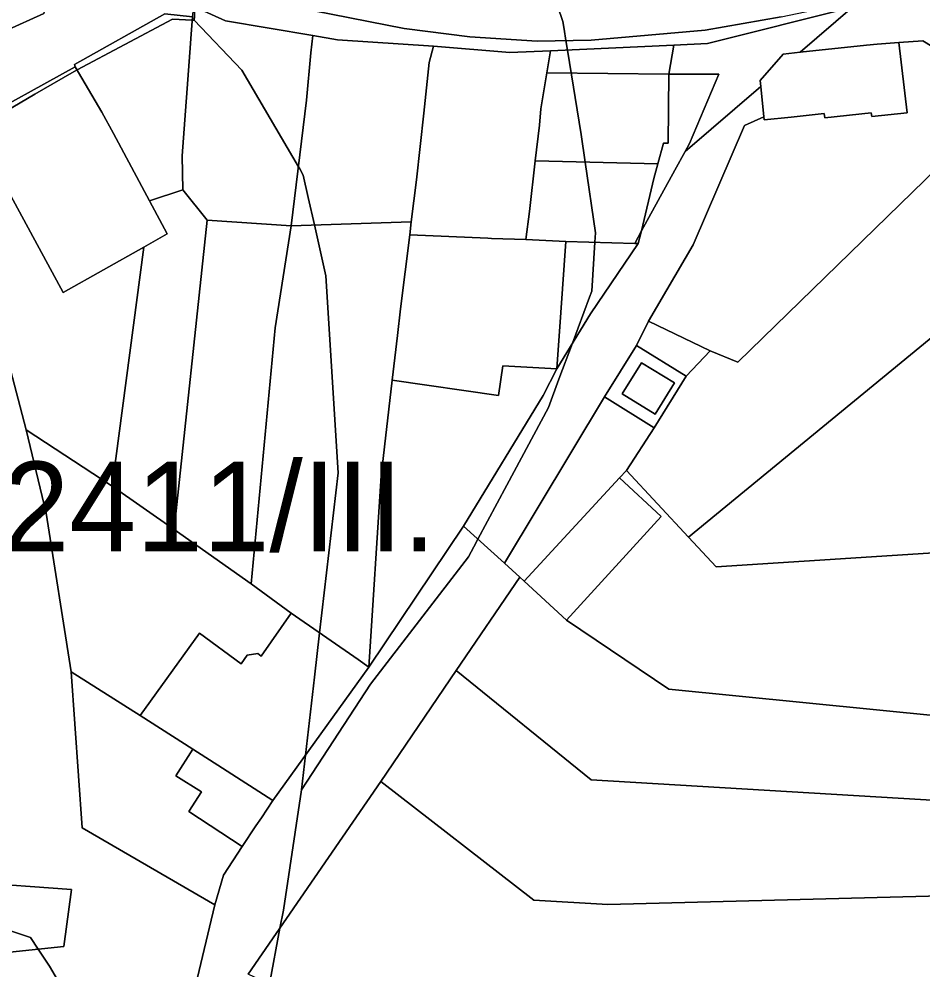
# Model space of a CAD drawing. Extents: x -522079 to -518792, y -1142400 to -1139961.
# Drawn here: x -520623.1 to -520471.9, y -1140957.2 to -1140798.1 of the extents above; entities that cross this region are included whole.
import ezdxf

# ---------------------------------------------------------------- set-up
doc = ezdxf.new("R2010")
doc.units = 0
for name, color, linetype in [('Hranice parcel', 7, 'Continuous'), ('Poz předměty', 7, 'Continuous'), ('Značky bodu BP', 7, 'Continuous'), ('Značky kultur', 7, 'Continuous')]:
    doc.layers.add(name, color=color, linetype=linetype)

msp = doc.modelspace()

# ---------------------------------------------------------------- linework, layer by layer
at = {"layer": 'Hranice parcel'}
for points in [[(-520616.33, -1140786.69), (-520618.93, -1140797.21), (-520638.22, -1140805.93), (-520641.11, -1140798.37), (-520652.69, -1140766.32), (-520657.82, -1140755.57), (-520666.3, -1140735.71), (-520669.12, -1140730.36), (-520634.59, -1140772.65)], [(-520573.94, -1140800.9), (-520588.57, -1140798.45), (-520593.85, -1140796.07), (-520595.39, -1140795.43), (-520594.41, -1140790.88), (-520587.36, -1140792.97), (-520573.73, -1140796.75), (-520558.67, -1140799.71), (-520547.7, -1140801.1), (-520536.39, -1140801.86), (-520527.36, -1140801.68), (-520508.3, -1140799.99), (-520495.6, -1140797.79), (-520487.57, -1140796.09), (-520477.93, -1140793.38), (-520477.5, -1140794.69), (-520478.64, -1140794.97), (-520483.65, -1140796.14), (-520507.9, -1140802.26), (-520513.53, -1140802.52), (-520534.2, -1140803.46), (-520540.96, -1140803.77), (-520553.77, -1140802.66), (-520569.82, -1140801.63)], [(-520479.52, -1140802.35), (-520481.31, -1140802.54), (-520492.42, -1140803.71), (-520483.65, -1140796.14), (-520478.64, -1140794.97), (-520477.5, -1140794.69), (-520471.14, -1140793.15), (-520469.2, -1140792.72), (-520462.48, -1140800.42), (-520444.45, -1140805.57), (-520456.93, -1140810.9), (-520471.87, -1140801.78), (-520475.9, -1140802.08)], [(-520574.26, -1140803.79), (-520575.01, -1140811.7), (-520577.54, -1140832.73), (-520591.61, -1140831.81), (-520595.7, -1140826.74), (-520595.78, -1140821.04), (-520594.39, -1140802.24), (-520594.33, -1140801.38), (-520594.09, -1140797.76), (-520593.85, -1140796.07), (-520588.57, -1140798.45), (-520573.94, -1140800.9)], [(-520510.91, -1140818.98), (-520506.04, -1140807.36), (-520514.4, -1140807.37), (-520513.53, -1140802.52), (-520507.9, -1140802.26), (-520483.65, -1140796.14), (-520492.42, -1140803.71), (-520495.25, -1140804.01), (-520499.12, -1140808.43), (-520499.02, -1140809.41), (-520511.64, -1140820.3)], [(-520613.67, -1140806.13), (-520613.82, -1140805.77), (-520598.71, -1140797.27), (-520594.09, -1140797.76), (-520594.33, -1140801.38), (-520594.39, -1140802.24), (-520595.78, -1140821.04), (-520595.7, -1140826.74), (-520601.28, -1140828.55), (-520607.3, -1140817.32), (-520609.23, -1140813.72)], [(-520573.94, -1140800.9), (-520569.82, -1140801.63), (-520553.77, -1140802.66), (-520554.47, -1140805.42), (-520555.39, -1140813.9), (-520556.61, -1140825.03), (-520557.47, -1140832.08), (-520577.54, -1140832.73), (-520575.01, -1140811.7), (-520574.26, -1140803.79)], [(-520507.49, -1140853.67), (-520517.77, -1140848.71), (-520510.31, -1140835.9), (-520501.75, -1140815.97), (-520498.5, -1140814.52), (-520498.45, -1140815.01), (-520493.9, -1140814.54), (-520488.38, -1140813.94), (-520488.31, -1140814.67), (-520480.51, -1140813.85), (-520480.44, -1140814.43), (-520474.54, -1140813.83), (-520475.9, -1140802.08), (-520471.87, -1140801.78), (-520456.93, -1140810.9), (-520502.85, -1140855.53)], [(-520540.96, -1140803.77), (-520534.2, -1140803.46), (-520534.78, -1140807.16), (-520535.78, -1140813.17), (-520536.03, -1140815.9), (-520536.72, -1140821.88), (-520537.7, -1140830.34), (-520538.32, -1140835.02), (-520544.03, -1140834.85), (-520544.69, -1140834.83), (-520557.73, -1140834.26), (-520557.47, -1140832.08), (-520556.61, -1140825.03), (-520555.39, -1140813.9), (-520554.47, -1140805.42), (-520553.77, -1140802.66)], [(-520534.78, -1140807.16), (-520534.2, -1140803.46), (-520513.53, -1140802.52), (-520514.4, -1140807.37)], [(-520488.38, -1140813.94), (-520493.9, -1140814.54), (-520498.45, -1140815.01), (-520498.5, -1140814.52), (-520499.02, -1140809.41), (-520499.12, -1140808.43), (-520495.25, -1140804.01), (-520492.42, -1140803.71), (-520481.31, -1140802.54), (-520479.52, -1140802.35), (-520475.9, -1140802.08), (-520474.54, -1140813.83), (-520480.44, -1140814.43), (-520480.51, -1140813.85), (-520488.31, -1140814.67)], [(-520615.7, -1140843.89), (-520626.71, -1140823.74), (-520631.12, -1140815.76), (-520613.67, -1140806.13), (-520609.23, -1140813.72), (-520607.3, -1140817.32), (-520601.28, -1140828.55), (-520598.3, -1140834.1), (-520602.23, -1140836.31)], [(-520536.72, -1140821.88), (-520536.03, -1140815.9), (-520535.78, -1140813.17), (-520534.78, -1140807.16), (-520514.4, -1140807.37), (-520514.48, -1140818.9), (-520515.29, -1140818.89), (-520516.23, -1140822.4)], [(-520514.4, -1140807.37), (-520506.04, -1140807.36), (-520510.91, -1140818.98), (-520511.64, -1140820.3), (-520513.38, -1140823.43), (-520518.98, -1140833.57), (-520516.87, -1140824.81), (-520516.23, -1140822.4), (-520515.29, -1140818.89), (-520514.48, -1140818.9)], [(-520511.64, -1140820.3), (-520499.02, -1140809.41), (-520498.5, -1140814.52), (-520501.75, -1140815.97), (-520510.31, -1140835.9), (-520517.77, -1140848.71), (-520519.8, -1140852.78), (-520525.13, -1140861.38), (-520541.88, -1140889.2), (-520548.74, -1140883.02), (-520535.38, -1140861.16), (-520533.13, -1140856.68), (-520527.5, -1140847.46), (-520519.49, -1140835.7), (-520518.98, -1140833.57), (-520513.38, -1140823.43)], [(-520542.88, -1140861.11), (-520560.66, -1140858.55), (-520559.8, -1140851.08), (-520559.29, -1140846.65), (-520557.73, -1140834.26), (-520544.69, -1140834.83), (-520544.03, -1140834.85), (-520538.32, -1140835.02), (-520531.62, -1140835.37), (-520532.45, -1140847.23), (-520533.13, -1140856.68), (-520542.18, -1140856.15)], [(-520517.77, -1140848.71), (-520507.49, -1140853.67), (-520511.48, -1140857.9), (-520519.8, -1140852.78)], [(-520519.8, -1140852.78), (-520511.48, -1140857.9), (-520516.84, -1140866.53), (-520525.13, -1140861.38)], [(-520518.94, -1140855.65), (-520513.44, -1140859.04), (-520516.67, -1140864.28), (-520522.17, -1140860.86)], [(-520513.44, -1140859.04), (-520518.94, -1140855.65), (-520522.17, -1140860.86), (-520516.67, -1140864.28)], [(-520516.84, -1140866.53), (-520521.46, -1140873.68), (-520522.62, -1140874.92), (-520538.57, -1140892.18), (-520539.31, -1140891.51), (-520541.88, -1140889.2), (-520525.13, -1140861.38)], [(-520538.57, -1140892.18), (-520522.62, -1140874.92), (-520515.64, -1140881.37), (-520531.52, -1140898.7)], [(-520602.83, -1140914.7), (-520592.91, -1140900.92), (-520585.91, -1140906.02), (-520584.9, -1140904.6), (-520583.16, -1140904.29), (-520582.61, -1140904.74), (-520577.55, -1140897.54), (-520566.38, -1140905.28), (-520564.56, -1140906.56), (-520580.62, -1140928.87), (-520589.05, -1140923.49), (-520594.01, -1140920.33)], [(-520596.85, -1140924.77), (-520594.01, -1140920.33), (-520589.05, -1140923.49), (-520580.62, -1140928.87), (-520582.55, -1140931.77), (-520583.47, -1140933.16), (-520585.74, -1140936.61), (-520594.7, -1140930.72), (-520592.56, -1140927.47)]]:
    msp.add_lwpolyline(points, close=True, dxfattribs=at)
for points in [[(-520638.22, -1140805.93), (-520618.93, -1140797.21), (-520616.33, -1140786.69), (-520595.39, -1140795.43), (-520593.85, -1140796.07), (-520594.09, -1140797.76), (-520598.71, -1140797.27), (-520613.82, -1140805.77), (-520613.67, -1140806.13), (-520631.12, -1140815.76)], [(-520495.6, -1140797.79), (-520508.3, -1140799.99), (-520527.36, -1140801.68), (-520536.39, -1140801.86), (-520547.7, -1140801.1), (-520558.67, -1140799.71), (-520573.73, -1140796.75)], [(-520594.75, -1140964.79), (-520590.36, -1140946.34), (-520588.9, -1140941.38), (-520585.74, -1140936.61), (-520583.47, -1140933.16), (-520582.55, -1140931.77), (-520580.62, -1140928.87), (-520564.56, -1140906.56), (-520548.74, -1140883.02), (-520541.88, -1140889.2), (-520539.31, -1140891.51), (-520549.95, -1140907.16), (-520562.58, -1140925.73), (-520584.75, -1140957.97)]]:
    msp.add_lwpolyline(points, dxfattribs=at)
at = {"layer": 'Poz předměty'}
for points in [[(-520679.92, -1141124.76), (-520699.09, -1140943.92), (-520632.04, -1140920.85), (-520634.37, -1140902.81), (-520641.23, -1140863.72), (-520646.19, -1140843.58), (-520650.7, -1140826.31), (-520634.79, -1140817.77), (-520621.9, -1140866.86), (-520618.56, -1140880.81), (-520614.37, -1140907.34), (-520612.5, -1140933.48), (-520590.36, -1140946.34), (-520594.75, -1140964.79), (-520649.51, -1140960.76), (-520648.03, -1140963.9), (-520620.51, -1141022.34), (-520612.04, -1141047.58), (-520596.21, -1141046.3), (-520599.33, -1141085.41), (-520603.47, -1141094.45), (-520605.48, -1141096), (-520676.95, -1141126.77)], [(-520614.33, -1140943.77), (-520648.15, -1140941.33), (-520646.42, -1140956.53), (-520615.62, -1140953.33)], [(-520615.62, -1140953.33), (-520646.42, -1140956.53), (-520648.15, -1140941.33), (-520614.33, -1140943.77)]]:
    msp.add_lwpolyline(points, close=True, dxfattribs=at)
at = {"layer": 'Značky bodu BP'}
for points in [[(-520626.64, -1140767.02), (-520622.14, -1140770.72), (-520612.6, -1140776.73), (-520595.12, -1140785.42), (-520594.75, -1140790.77), (-520594.66, -1140792.05), (-520594.4, -1140795.84), (-520594.34, -1140796.75), (-520593.97, -1140796.89), (-520593.9, -1140796.91), (-520593.71, -1140796.98), (-520593.74, -1140797.73), (-520593.77, -1140798.35), (-520594.13, -1140798.33), (-520597.42, -1140798.15), (-520613.36, -1140806.66), (-520614.24, -1140807.13), (-520620.42, -1140810.73), (-520630.61, -1140816.68)], [(-520533.02, -1140795.94), (-520532.11, -1140798.57), (-520531.9, -1140799.83), (-520531.59, -1140801.76), (-520531.34, -1140803.33), (-520529.07, -1140817.46), (-520528.39, -1140822.09), (-520526.64, -1140833.91), (-520526.74, -1140835.5), (-520527.25, -1140843.66), (-520527.64, -1140844.7), (-520530.51, -1140852.4), (-520532.76, -1140858.41), (-520534.54, -1140863.15), (-520541.46, -1140876.11), (-520546.32, -1140885.19), (-520547, -1140886.46), (-520547.9, -1140888.13), (-520564.3, -1140909.45), (-520575.83, -1140927.12), (-520575.16, -1140921.29), (-520573.66, -1140908.26), (-520572.8, -1140900.83), (-520569.72, -1140874.1), (-520571.78, -1140841.09), (-520572.55, -1140837.61), (-520573.67, -1140832.6), (-520574.7, -1140828), (-520575.55, -1140824.25), (-520576.14, -1140823.23), (-520576.35, -1140822.87), (-520585.83, -1140806.71), (-520593.77, -1140798.35), (-520593.74, -1140797.73)], [(-520581.21, -1140959.64), (-520579.44, -1140950.25), (-520578.87, -1140947.23), (-520575.83, -1140927.12), (-520564.3, -1140909.45), (-520547.9, -1140888.13), (-520547, -1140886.46), (-520546.32, -1140885.19), (-520541.46, -1140876.11), (-520534.54, -1140863.15), (-520532.76, -1140858.41), (-520530.51, -1140852.4), (-520527.64, -1140844.7), (-520527.25, -1140843.66), (-520526.74, -1140835.5), (-520526.64, -1140833.91), (-520528.39, -1140822.09), (-520529.07, -1140817.46), (-520531.34, -1140803.33), (-520531.59, -1140801.76), (-520531.9, -1140799.83), (-520532.11, -1140798.57), (-520533.02, -1140795.94)], [(-520630.61, -1140816.68), (-520620.42, -1140810.73), (-520614.24, -1140807.13), (-520613.36, -1140806.66), (-520597.42, -1140798.15), (-520594.13, -1140798.33), (-520593.77, -1140798.35), (-520585.83, -1140806.71), (-520576.35, -1140822.87), (-520576.14, -1140823.23), (-520575.55, -1140824.25), (-520574.7, -1140828), (-520573.67, -1140832.6), (-520572.55, -1140837.61), (-520571.78, -1140841.09), (-520569.72, -1140874.1), (-520572.8, -1140900.83), (-520573.66, -1140908.26), (-520575.16, -1140921.29), (-520575.83, -1140927.12), (-520578.87, -1140947.23), (-520579.44, -1140950.25), (-520581.21, -1140959.64)], [(-520627.56, -1140949.7), (-520621.19, -1140951.83), (-520619.9, -1140953.77), (-520618, -1140956.63), (-520614.03, -1140963.37), (-520612.45, -1140966.05), (-520611.1, -1140968.35), (-520603.66, -1140990.19), (-520600.09, -1141003.03), (-520598.92, -1141007.25), (-520592.23, -1141031.31), (-520592.74, -1141051.53), (-520593.45, -1141079.44), (-520594.66, -1141123.3), (-520594.45, -1141124.94), (-520594.12, -1141127.62), (-520593.85, -1141129.76), (-520589.2, -1141166.56), (-520587.79, -1141182.35)], [(-520614.03, -1140963.37), (-520618, -1140956.63), (-520619.9, -1140953.77), (-520621.19, -1140951.83), (-520627.56, -1140949.7)]]:
    msp.add_lwpolyline(points, dxfattribs=at)
at = {"layer": 'Značky kultur'}
for points in [[(-520511.48, -1140857.9), (-520507.49, -1140853.67), (-520502.85, -1140855.53), (-520456.93, -1140810.9), (-520454.35, -1140812.75), (-520438.39, -1140825.08), (-520511.12, -1140884.82), (-520521.46, -1140873.68), (-520516.84, -1140866.53)], [(-520607.5, -1140876.29), (-520621.9, -1140866.86), (-520634.79, -1140817.77), (-520631.12, -1140815.76), (-520626.71, -1140823.74), (-520615.7, -1140843.89), (-520602.23, -1140836.31)], [(-520537.7, -1140830.34), (-520536.72, -1140821.88), (-520516.23, -1140822.4), (-520516.87, -1140824.81), (-520518.98, -1140833.57), (-520520.1, -1140835.68), (-520531.62, -1140835.37), (-520538.32, -1140835.02)], [(-520431.21, -1140855.94), (-520431.14, -1140872), (-520434.57, -1140885.18), (-520506.49, -1140889.8), (-520511.12, -1140884.82), (-520438.39, -1140825.08), (-520423.56, -1140836.55), (-520420.15, -1140839.19), (-520420.46, -1140841.58), (-520429.98, -1140844.23)], [(-520598.3, -1140834.1), (-520601.28, -1140828.55), (-520595.7, -1140826.74), (-520591.61, -1140831.81), (-520597.12, -1140883.57), (-520607.5, -1140876.29), (-520602.23, -1140836.31)], [(-520577.54, -1140832.73), (-520580.23, -1140849.82), (-520584.23, -1140892.62), (-520597.12, -1140883.57), (-520591.61, -1140831.81)], [(-520557.73, -1140834.26), (-520559.29, -1140846.65), (-520559.8, -1140851.08), (-520560.66, -1140858.55), (-520562.5, -1140874.6), (-520564.56, -1140906.56), (-520566.38, -1140905.28), (-520577.55, -1140897.54), (-520584.23, -1140892.62), (-520580.23, -1140849.82), (-520577.54, -1140832.73), (-520557.47, -1140832.08)], [(-520518.98, -1140833.57), (-520519.49, -1140835.7), (-520520.1, -1140835.68)], [(-520531.62, -1140835.37), (-520520.1, -1140835.68), (-520519.49, -1140835.7), (-520527.5, -1140847.46), (-520533.13, -1140856.68), (-520532.45, -1140847.23)], [(-520548.74, -1140883.02), (-520564.56, -1140906.56), (-520562.5, -1140874.6), (-520560.66, -1140858.55), (-520542.88, -1140861.11), (-520542.18, -1140856.15), (-520533.13, -1140856.68), (-520535.38, -1140861.16)], [(-520602.83, -1140914.7), (-520614.37, -1140907.34), (-520618.56, -1140880.81), (-520621.9, -1140866.86), (-520607.5, -1140876.29), (-520597.12, -1140883.57), (-520584.23, -1140892.62), (-520577.55, -1140897.54), (-520582.61, -1140904.74), (-520583.16, -1140904.29), (-520584.9, -1140904.6), (-520585.91, -1140906.02), (-520592.91, -1140900.92)], [(-520430.59, -1140910.8), (-520451.95, -1140915.2), (-520468.41, -1140914.85), (-520514.41, -1140910.27), (-520531.52, -1140898.7), (-520515.64, -1140881.37), (-520522.62, -1140874.92), (-520521.46, -1140873.68), (-520511.12, -1140884.82), (-520506.49, -1140889.8), (-520434.57, -1140885.18)], [(-520438.64, -1140930.72), (-520527.38, -1140925.42), (-520549.95, -1140907.16), (-520539.31, -1140891.51), (-520538.57, -1140892.18), (-520531.52, -1140898.7), (-520514.41, -1140910.27), (-520468.41, -1140914.85), (-520451.95, -1140915.2), (-520430.59, -1140910.8), (-520429.5, -1140919.57), (-520431.36, -1140926.59), (-520436.87, -1140928.43)], [(-520585.74, -1140936.61), (-520588.9, -1140941.38), (-520590.36, -1140946.34), (-520612.5, -1140933.48), (-520614.37, -1140907.34), (-520602.83, -1140914.7), (-520594.01, -1140920.33), (-520596.85, -1140924.77), (-520592.56, -1140927.47), (-520594.7, -1140930.72)], [(-520449.47, -1140944.32), (-520524.57, -1140946.3), (-520536.98, -1140945.57), (-520562.58, -1140925.73), (-520549.95, -1140907.16), (-520527.38, -1140925.42), (-520438.64, -1140930.72)], [(-520529.52, -1140984.06), (-520584.75, -1140957.97), (-520562.58, -1140925.73), (-520536.98, -1140945.57), (-520524.57, -1140946.3), (-520449.47, -1140944.32), (-520446.79, -1140958), (-520453.28, -1140975.93), (-520475.75, -1140979.18), (-520509.19, -1140985.26), (-520518.62, -1140988.49)]]:
    msp.add_lwpolyline(points, close=True, dxfattribs=at)

# ---------------------------------------------------------------- texts
at = {"layer": 'Značky bodu BP'}
msp.add_text('62411/III.', height=15, rotation=360, dxfattribs=at).set_placement((-520636.98, -1140887.21))

doc.saveas('drawing.dxf')
